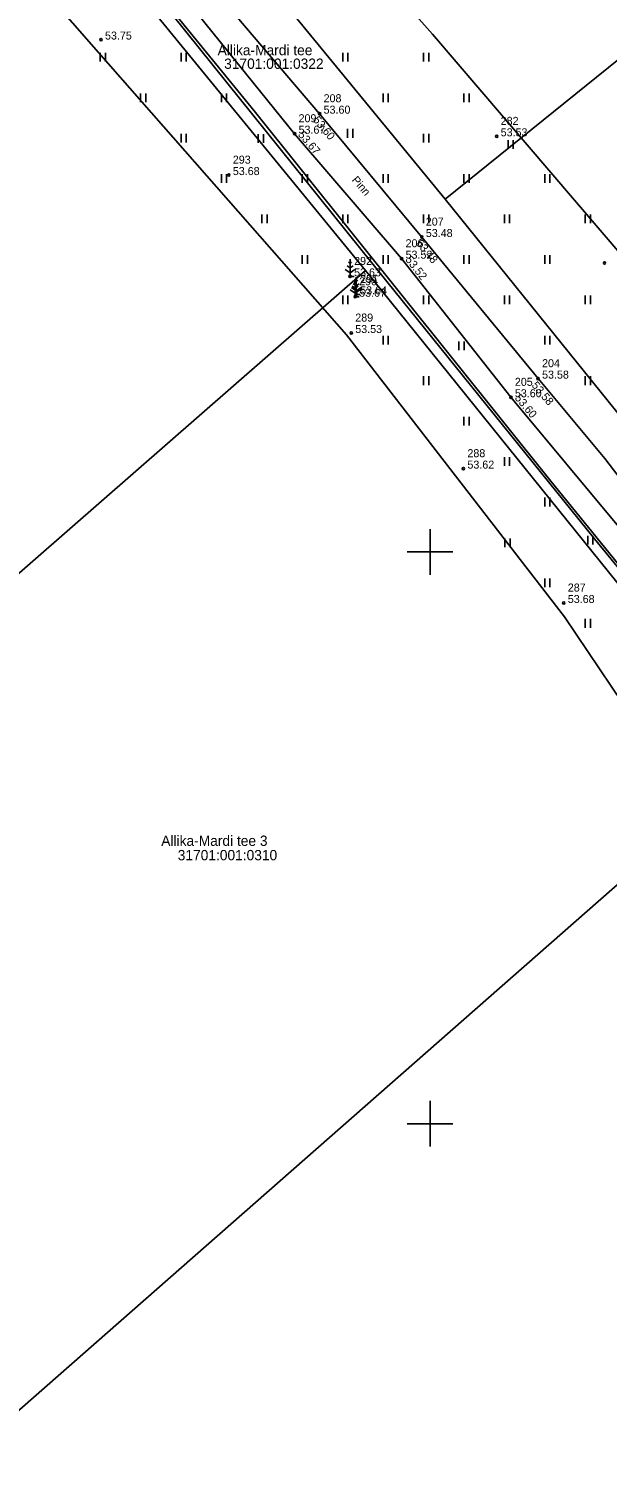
# Model space of a CAD drawing. Extents: x 538599 to 541973, y 6559689 to 6564516.
# Drawn here: x 540464.9 to 540515.5, y 6561220.1 to 6561345.8 of the extents above; entities that cross this region are included whole.
import ezdxf

# ---------------------------------------------------------------- set-up
doc = ezdxf.new("R2010")
doc.units = 0
for name, color, linetype in [('HALJASTUS', 7, 'Continuous'), ('KORGUS-EH2000', 7, 'Continuous'), ('KPKAABEL', 7, 'Continuous'), ('MOOTKORG-EH2000', 7, 'Continuous'), ('MOOTMPUNKT', 7, 'Continuous'), ('MOOTNR', 7, 'Continuous'), ('MOOTPIIR', 7, 'Continuous'), ('MPKAABEL', 7, 'Continuous'), ('PIIR', 7, 'Continuous'), ('PUU', 7, 'Continuous'), ('TEE', 7, 'Continuous'), ('VORK', 7, 'Continuous')]:
    doc.layers.add(name, color=color, linetype=linetype)

msp = doc.modelspace()

# ---------------------------------------------------------------- linework, layer by layer
at = {"layer": 'HALJASTUS'}
for p, q in [((540471.15, 6561343.64), (540471.15, 6561342.88)), ((540471.6, 6561343.64), (540471.6, 6561342.88)), ((540478.22, 6561343.64), (540478.22, 6561342.88)), ((540478.67, 6561343.64), (540478.67, 6561342.88)), ((540492.36, 6561343.64), (540492.36, 6561342.88)), ((540492.81, 6561343.64), (540492.81, 6561342.88)), ((540499.43, 6561343.64), (540499.43, 6561342.88)), ((540499.89, 6561343.64), (540499.89, 6561342.88)), ((540474.68, 6561340.1), (540474.68, 6561339.34)), ((540475.14, 6561340.1), (540475.14, 6561339.34)), ((540481.75, 6561340.1), (540481.75, 6561339.34)), ((540482.21, 6561340.1), (540482.21, 6561339.34)), ((540495.89, 6561340.1), (540495.89, 6561339.34)), ((540496.35, 6561340.1), (540496.35, 6561339.34)), ((540502.97, 6561340.1), (540502.97, 6561339.34)), ((540503.42, 6561340.1), (540503.42, 6561339.34)), ((540478.22, 6561336.57), (540478.22, 6561335.81)), ((540478.67, 6561336.57), (540478.67, 6561335.81)), ((540484.97, 6561336.54), (540484.97, 6561335.77)), ((540485.42, 6561336.54), (540485.42, 6561335.77)), ((540492.79, 6561336.99), (540492.79, 6561336.23)), ((540493.25, 6561336.99), (540493.25, 6561336.23)), ((540499.43, 6561336.57), (540499.43, 6561335.81)), ((540499.89, 6561336.57), (540499.89, 6561335.81)), ((540506.82, 6561336.01), (540506.82, 6561335.25)), ((540507.27, 6561336.01), (540507.27, 6561335.25)), ((540481.75, 6561333.03), (540481.75, 6561332.27)), ((540482.21, 6561333.03), (540482.21, 6561332.27)), ((540488.82, 6561333.03), (540488.82, 6561332.27)), ((540489.28, 6561333.03), (540489.28, 6561332.27)), ((540495.89, 6561333.03), (540495.89, 6561332.27)), ((540496.35, 6561333.03), (540496.35, 6561332.27)), ((540502.97, 6561333.03), (540502.97, 6561332.27)), ((540503.42, 6561333.03), (540503.42, 6561332.27)), ((540510.04, 6561333.03), (540510.04, 6561332.27)), ((540510.49, 6561333.03), (540510.49, 6561332.27)), ((540485.29, 6561329.5), (540485.29, 6561328.74)), ((540485.74, 6561329.5), (540485.74, 6561328.74)), ((540492.36, 6561329.5), (540492.36, 6561328.74)), ((540492.81, 6561329.5), (540492.81, 6561328.74)), ((540499.43, 6561329.5), (540499.43, 6561328.74)), ((540499.89, 6561329.5), (540499.89, 6561328.74)), ((540506.5, 6561329.5), (540506.5, 6561328.74)), ((540506.96, 6561329.5), (540506.96, 6561328.74)), ((540513.57, 6561329.5), (540513.57, 6561328.74)), ((540514.03, 6561329.5), (540514.03, 6561328.74)), ((540488.82, 6561325.96), (540488.82, 6561325.2)), ((540489.28, 6561325.96), (540489.28, 6561325.2)), ((540495.89, 6561325.96), (540495.89, 6561325.2)), ((540496.35, 6561325.96), (540496.35, 6561325.2)), ((540502.97, 6561325.96), (540502.97, 6561325.2)), ((540503.42, 6561325.96), (540503.42, 6561325.2)), ((540510.04, 6561325.96), (540510.04, 6561325.2)), ((540510.49, 6561325.96), (540510.49, 6561325.2)), ((540492.36, 6561322.43), (540492.36, 6561321.67)), ((540492.81, 6561322.43), (540492.81, 6561321.67)), ((540499.43, 6561322.43), (540499.43, 6561321.67)), ((540499.89, 6561322.43), (540499.89, 6561321.67)), ((540506.5, 6561322.43), (540506.5, 6561321.67)), ((540506.96, 6561322.43), (540506.96, 6561321.67)), ((540513.57, 6561322.43), (540513.57, 6561321.67)), ((540514.03, 6561322.43), (540514.03, 6561321.67)), ((540495.89, 6561318.89), (540495.89, 6561318.13)), ((540496.35, 6561318.89), (540496.35, 6561318.13)), ((540510.04, 6561318.89), (540510.04, 6561318.13)), ((540510.49, 6561318.89), (540510.49, 6561318.13)), ((540502.53, 6561318.41), (540502.53, 6561317.65)), ((540502.98, 6561318.41), (540502.98, 6561317.65)), ((540499.43, 6561315.36), (540499.43, 6561314.59)), ((540499.89, 6561315.36), (540499.89, 6561314.59)), ((540513.57, 6561315.36), (540513.57, 6561314.59)), ((540514.03, 6561315.36), (540514.03, 6561314.59)), ((540502.97, 6561311.82), (540502.97, 6561311.06)), ((540503.42, 6561311.82), (540503.42, 6561311.06)), ((540506.5, 6561308.28), (540506.5, 6561307.52)), ((540506.96, 6561308.28), (540506.96, 6561307.52)), ((540510.04, 6561304.75), (540510.04, 6561303.99)), ((540510.49, 6561304.75), (540510.49, 6561303.99)), ((540506.54, 6561301.17), (540506.54, 6561300.41)), ((540507, 6561301.17), (540507, 6561300.41)), ((540513.79, 6561301.41), (540513.79, 6561300.65)), ((540514.24, 6561301.41), (540514.24, 6561300.65)), ((540510.04, 6561297.68), (540510.04, 6561296.92)), ((540510.49, 6561297.68), (540510.49, 6561296.92)), ((540513.57, 6561294.14), (540513.57, 6561293.38)), ((540514.03, 6561294.14), (540514.03, 6561293.38))]:
    msp.add_line(p, q, dxfattribs=at)
at = {"layer": 'KORGUS-EH2000'}
for centre in [(540471.22, 6561344.81), (540490.34, 6561338.33), (540488.15, 6561336.58), (540505.83, 6561336.35), (540482.4, 6561332.96), (540499.28, 6561327.54), (540497.51, 6561325.65), (540515.26, 6561325.27), (540493.11, 6561319.15), (540509.45, 6561315.16), (540507.07, 6561313.53), (540502.92, 6561307.29), (540511.7, 6561295.54)]:
    msp.add_circle(centre, 0.1, dxfattribs=at)
at = {"layer": 'KPKAABEL'}
msp.add_lwpolyline([(540612.71, 6561251.64), (540589.75, 6561235.92), (540575.11, 6561226.32), (540574.31, 6561226.49), (540572.81, 6561227.65), (540566.99, 6561234.12), (540563.29, 6561239.03), (540553.8, 6561251.29), (540538.41, 6561271.22), (540529.49, 6561282.51), (540526.27, 6561286.88), (540510.56, 6561306.2), (540484.62, 6561338.57), (540463.55, 6561364.4), (540438.89, 6561393.7), (540425.44, 6561409.21), (540424.92, 6561409.46), (540423.73, 6561408.81), (540421.72, 6561406.34), (540419.82, 6561404.72)], dxfattribs=at)
at = {"layer": 'MOOTMPUNKT'}
for centre in [(540471.22, 6561344.81), (540490.34, 6561338.33), (540488.15, 6561336.58), (540505.83, 6561336.35), (540482.4, 6561332.96), (540499.28, 6561327.54), (540497.51, 6561325.65), (540515.26, 6561325.27), (540493.01, 6561324.1), (540493.54, 6561322.53), (540493.45, 6561322.32), (540493.11, 6561319.15), (540509.45, 6561315.16), (540507.07, 6561313.53), (540502.92, 6561307.29), (540511.7, 6561295.54)]:
    msp.add_circle(centre, 0.1, dxfattribs=at)
at = {"layer": 'MOOTPIIR'}
for points in [[(540611.81, 6561347.63), (540600.55, 6561344.05), (540588.99, 6561338.31), (540579.51, 6561329.75), (540567.37, 6561324.71), (540557.3, 6561315.5), (540537.55, 6561303.29), (540525.23, 6561316.05), (540500.22, 6561345.28), (540476.49, 6561372), (540449.03, 6561405.28), (540428.79, 6561428.29), (540413.02, 6561448.22), (540405.1, 6561459.89), (540393.81, 6561473.15)], [(540384.89, 6561443.84), (540403.97, 6561422.47), (540424.3, 6561399.7), (540444.64, 6561376.93), (540453.18, 6561363.99), (540470.99, 6561343.69), (540492.69, 6561318.98), (540511.77, 6561294.34), (540521.97, 6561279.18), (540525.59, 6561267.95), (540536.49, 6561252.79), (540542.77, 6561231.93), (540526.6, 6561219.05), (540510.62, 6561213.47), (540498.26, 6561199.2), (540484.56, 6561192.98), (540479.62, 6561185.62), (540478.41, 6561178.33), (540490.46, 6561165.83), (540493.58, 6561162.6), (540531.11, 6561187.91), (540582.87, 6561222.82), (540621.74, 6561247.75)]]:
    msp.add_lwpolyline(points, dxfattribs=at)
at = {"layer": 'MPKAABEL'}
msp.add_lwpolyline([(540624.75, 6561259.65), (540607.46, 6561247.73), (540595.99, 6561239.88), (540585.36, 6561232.86), (540575.16, 6561226.11), (540574.21, 6561226.3), (540572.67, 6561227.5), (540566.84, 6561233.99), (540559.42, 6561243.82), (540553.65, 6561251.16), (540543.07, 6561264.8), (540529.49, 6561282.18), (540528.9, 6561282.25), (540529.18, 6561282.59), (540526.04, 6561286.86), (540522.47, 6561291.3), (540514.38, 6561301.15), (540496.22, 6561323.66), (540475.17, 6561349.87)], dxfattribs=at)
at = {"layer": 'PIIR'}
for points in [[(540491.21, 6561183.5), (540566.07, 6561233.36), (540528.84, 6561281.85), (540494.34, 6561324.62), (540458.27, 6561368.69), (540424.68, 6561408.57), (540384.55, 6561455.73), (540346.17, 6561499.11), (540330.12, 6561517.14), (540337.36, 6561523.32), (540348.28, 6561532.96), (540364.11, 6561514.94), (540353.14, 6561505.27), (540391.51, 6561461.86), (540431.74, 6561414.74), (540465.17, 6561374.89), (540501.31, 6561330.86), (540535.92, 6561287.97), (540573.77, 6561238.75), (540640.63, 6561283.66), (540646.74, 6561272.89), (540499, 6561174.36)], [(540465.17, 6561374.89), (540537.11, 6561431.06), (540569.6, 6561385.93), (540501.31, 6561330.86)], [(540501.31, 6561330.86), (540569.6, 6561385.93), (540606.26, 6561333.96), (540535.92, 6561287.97)], [(540384.73, 6561304.57), (540458.27, 6561368.69), (540494.34, 6561324.62), (540422.29, 6561261.69)], [(540422.29, 6561261.69), (540494.34, 6561324.62), (540528.84, 6561281.85), (540458.8, 6561220.37)], [(540458.8, 6561220.37), (540528.84, 6561281.85), (540566.07, 6561233.36), (540491.21, 6561183.5)]]:
    msp.add_lwpolyline(points, close=True, dxfattribs=at)
at = {"layer": 'PUU'}
for p, q in [((540493.01, 6561325.25), (540492.88, 6561325.33)), ((540493.01, 6561325.6), (540493.01, 6561324.1)), ((540493.13, 6561325.33), (540493.01, 6561325.25)), ((540492.58, 6561324.69), (540493.01, 6561324.4)), ((540493.01, 6561324.85), (540492.74, 6561325.02)), ((540493.28, 6561325.02), (540493.01, 6561324.85)), ((540493.01, 6561324.4), (540493.43, 6561324.69)), ((540493.37, 6561324.1), (540493.01, 6561324.1)), ((540493.45, 6561323.82), (540493.45, 6561322.32)), ((540493.54, 6561324.03), (540493.54, 6561322.53)), ((540493.02, 6561322.91), (540493.45, 6561322.63)), ((540493.12, 6561323.12), (540493.54, 6561322.84)), ((540493.45, 6561323.07), (540493.18, 6561323.25)), ((540493.54, 6561323.28), (540493.28, 6561323.46)), ((540493.45, 6561323.47), (540493.32, 6561323.56)), ((540493.54, 6561323.68), (540493.42, 6561323.76)), ((540493.57, 6561323.56), (540493.45, 6561323.47)), ((540493.71, 6561323.25), (540493.45, 6561323.07)), ((540493.45, 6561322.63), (540493.87, 6561322.91)), ((540493.67, 6561323.76), (540493.54, 6561323.68)), ((540493.81, 6561323.46), (540493.54, 6561323.28)), ((540493.54, 6561322.84), (540493.97, 6561323.12)), ((540493.9, 6561322.53), (540493.54, 6561322.53)), ((540493.81, 6561322.32), (540493.45, 6561322.32))]:
    msp.add_line(p, q, dxfattribs=at)
at = {"layer": 'TEE'}
for points in [[(540480.24, 6561350.17), (540490.34, 6561338.33), (540499.28, 6561327.54), (540509.45, 6561315.16), (540515.3, 6561308.18), (540518.54, 6561303.94), (540527.78, 6561291.78), (540530.57, 6561288.24), (540536.21, 6561281.56), (540545.98, 6561268.79), (540548.21, 6561265.82), (540555.65, 6561256.76), (540560.73, 6561250.31), (540563.9, 6561245.79), (540566.42, 6561241.84), (540570.09, 6561235.28), (540571.31, 6561233.9), (540572.29, 6561233.08), (540574.39, 6561231.79), (540575.62, 6561231.66), (540576.37, 6561231.99), (540586.54, 6561238.83), (540599.72, 6561247.48), (540611.44, 6561255.6)], [(540551.36, 6561215.46), (540563.47, 6561223.95), (540565.77, 6561225.92), (540567.47, 6561228.12), (540568.24, 6561229.6), (540568.59, 6561231.91), (540567.95, 6561233.46), (540564.97, 6561239.31), (540561.94, 6561244.37), (540554.08, 6561254.97), (540546.91, 6561263.45), (540543.75, 6561267.55), (540534.5, 6561279.78), (540528.67, 6561286.52), (540525.77, 6561290.15), (540516.79, 6561301.88), (540507.07, 6561313.53), (540497.51, 6561325.65), (540488.15, 6561336.58), (540478.59, 6561348.43)]]:
    msp.add_lwpolyline(points, dxfattribs=at)
at = {"layer": 'VORK'}
for p, q in [((540500, 6561302), (540500, 6561298)), ((540498, 6561300), (540502, 6561300)), ((540500, 6561252), (540500, 6561248)), ((540498, 6561250), (540502, 6561250))]:
    msp.add_line(p, q, dxfattribs=at)

# ---------------------------------------------------------------- texts
at = {"layer": 'KORGUS-EH2000'}
for s, p in [('53.75', (540471.57, 6561344.81)), ('53.53', (540506.18, 6561336.35)), ('53.68', (540482.75, 6561332.96)), ('53.53', (540493.46, 6561319.15)), ('53.62', (540503.27, 6561307.29)), ('53.68', (540512.05, 6561295.54))]:
    msp.add_text(s, height=0.7, dxfattribs=at).set_placement(p)
for s, rotation, p in [('53.60', 309.6302, (540489.72, 6561337.76)), ('53.67', 310.5469, (540488.41, 6561336.46)), ('53.48', 309.4059, (540498.72, 6561326.97)), ('53.52', 308.2998, (540497.8, 6561325.55)), ('53.60', 309.8177, (540507.37, 6561313.44)), ('53.58', 309.9757, (540508.84, 6561314.55))]:
    msp.add_text(s, height=0.7, rotation=rotation, dxfattribs=at).set_placement(p)
at = {"layer": 'MOOTKORG-EH2000'}
for s, p in [('53.75', (540471.57, 6561344.81)), ('53.60', (540490.69, 6561338.33)), ('53.67', (540488.5, 6561336.58)), ('53.53', (540506.18, 6561336.35)), ('53.68', (540482.75, 6561332.96)), ('53.48', (540499.63, 6561327.54)), ('53.52', (540497.86, 6561325.65)), ('53.63', (540493.36, 6561324.1)), ('53.67', (540493.8, 6561322.32)), ('53.64', (540493.89, 6561322.53)), ('53.53', (540493.46, 6561319.15)), ('53.58', (540509.8, 6561315.16)), ('53.60', (540507.42, 6561313.53)), ('53.62', (540503.27, 6561307.29)), ('53.68', (540512.05, 6561295.54))]:
    msp.add_text(s, height=0.7, dxfattribs=at).set_placement(p)
at = {"layer": 'MOOTNR'}
for s, p in [('208', (540490.69, 6561339.33)), ('209', (540488.5, 6561337.58)), ('282', (540506.18, 6561337.35)), ('293', (540482.75, 6561333.96)), ('207', (540499.63, 6561328.54)), ('206', (540497.86, 6561326.65)), ('292', (540493.36, 6561325.1)), ('290', (540493.8, 6561323.32)), ('291', (540493.89, 6561323.53)), ('289', (540493.46, 6561320.15)), ('204', (540509.8, 6561316.16)), ('205', (540507.42, 6561314.53)), ('288', (540503.27, 6561308.29)), ('287', (540512.05, 6561296.54))]:
    msp.add_text(s, height=0.7, dxfattribs=at).set_placement(p)
at = {"layer": 'PIIR'}
for s, p in [('Allika-Mardi tee', (540481.42, 6561343.44)), ('31701:001:0322', (540481.99, 6561342.25)), ('Allika-Mardi tee 3', (540476.49, 6561274.3)), ('31701:001:0310', (540477.93, 6561273.04))]:
    msp.add_text(s, height=0.9, rotation=0, dxfattribs=at).set_placement(p)
at = {"layer": 'TEE'}
msp.add_text('Pinn', height=0.7, rotation=310.5469, dxfattribs=at).set_placement((540493.11, 6561332.5))

doc.saveas('drawing.dxf')
